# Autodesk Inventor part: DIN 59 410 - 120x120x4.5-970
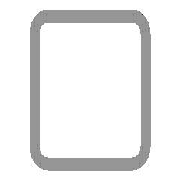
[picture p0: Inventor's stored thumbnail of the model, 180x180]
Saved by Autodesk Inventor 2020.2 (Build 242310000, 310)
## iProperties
Manager: www.cadconsulting.pl
Company: Fabian Stasiak CAD Consulting
IsCustomPart: 1
_CCFamilyMember: 200
_CCFamilyDisplayName: DIN 59410 (Kwadrat) - Rurki stalowe o przekroju kwadratowym formowane na gorąco — Standard DIN 59410 (Kwadrat) został wycofany i zastąpiony przez standard DIN E
_FrameMemberDoc: Frame Member File
_Version: 15.0.0
_GetPNFromCC: 1
Created: 2015-02
Part Number: DIN 59 410 - 120x120x4.5-970
Material: Stal, miękka
Description: Rurki stalowe o przekroju kwadratowym formowane na gorąco
Document SubType Name: Modellieren
Standard: DIN
Designer: F.Stasiak
Standards Organization: DIN
Language: pl-PL
Size Designation: 120x120x4.5
Categories: <MemberInstance><Categories><Category DisplayName="Kształtowniki konstrukcyjne" InternalName="089c4875-fa83-4c05-b084-43b9cc11f5ed" Mnemonic="GRDR"><CategoryPar
Stock Number: 120x120x4.5
Density: 7.85 g/cm^3
Appearance: Częściowo polerowany
Catalog Web Link: www.expertbooks.pl
G_L: 970,000 mm
G_W: 120,000 mm
G_H: 120,000 mm
+7B8C03AB-87A0-44DB-8815-7752895BC40E+CUTDETAIL1: Wytnij
+AA4B89D5-78A4-47A5-95B3-D9CF6164BA30+CUTDETAIL2: Wytnij
Author: F.Stasiak
Subject: Zbiór ćwiczeń. Autodesk Inventor 2020. Kurs Professional
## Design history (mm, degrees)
node "Płaszczyzna początkowa"
node "Płaszczyzna końcowa"
sketch "Szkic"
  geometry: L1 (-51, 60)-(51, 60); L2 (60, 51)-(60, -51); L3 (51, -60)-(-51, -60); L4 (-60, -51)-(-60, 51); L5 (-86.61, 0)-(86.61, 0) reference; L6 (0, -86.61)-(0, 86.61) reference; L7 (-51, 55.5)-(51, 55.5); L8 (55.5, 51)-(55.5, -51); L9 (51, -55.5)-(-51, -55.5); L10 (-55.5, -51)-(-55.5, 51); A1 r 9 centre (-51, 51) between (-51, 60) and (-60, 51); A2 r 9 centre (51, 51) between (60, 51) and (51, 60); A3 r 9 centre (51, -51) between (51, -60) and (60, -51); A4 r 9 centre (-51, -51) between (-60, -51) and (-51, -60); A5 r 4.5 centre (-51, 51) between (-51, 55.5) and (-55.5, 51); A6 r 4.5 centre (51, 51) between (55.5, 51) and (51, 55.5); A7 r 4.5 centre (51, -51) between (51, -55.5) and (55.5, -51); A8 r 4.5 centre (-51, -51) between (-55.5, -51) and (-51, -55.5); 3 further points
  constraints: 16 end point, 16 point on circle, 8 centre point, 8 tangent, 6 point on line, 4 parallel, 3 equal radius, 3 perpendicular, 1 horizontal, 7 other
  dimensions: "b" = 120 distance of point (-60, 60) point (60, 60); "msp_r" = 9 radius of A1 (= 2 x ParT); "d8" = 60 distance between parallel lines of L4 L6 (= d9); "d9" = 60 distance between parallel lines of L3 L5 (= 0.5 x b); "d10" = 4.5 distance between parallel lines of L3 L9 (= ParT)
extrude "Bryła" new body sketch "Szkic" taper "d4" = 0 deg; stored distance "NLG" = 10
node "Driven Length"
  sketch "Sketch2"
    geometry: L1 (0, 0)-(10, 0) reference
    constraints: 2 end point, 1 horizontal
  workplane "Work Plane3"
  sketch "Sketch3"
    geometry: L1 (-2, 60)-(12, 60) reference; L2 (-2, 1030)-(12, 1030) reference
    dimensions: "d14" = 970 distance between parallel lines of L1 L2 (derived)
node "Płaszczyzna konstrukcyjna4"
feature "Podział1"
node "Płaszczyzna konstrukcyjna5"
feature "Podział2"
body "Solid1"
other parameters: "ParT" = 4.5, "G_L" = 970 (= d14) [user parameter], "d13" = 90 deg
